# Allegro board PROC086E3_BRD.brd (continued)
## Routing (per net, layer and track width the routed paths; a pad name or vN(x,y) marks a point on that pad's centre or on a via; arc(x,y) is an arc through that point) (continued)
LI_VIN_DATA2: length 23.7
  TOP w0.178: v1(60.07,185.11) 60.07,184.77 59.89,184.59 59.28,184.59 58.92,184.23 58.92,181.87 59.26,181.53 60.45,181.53 60.6,181.38 60.6,181.16 60.45,181 59.26,181 59.11,180.84 59.11,180.62 59.26,180.47 60.45,180.47 60.6,180.31 60.6,180.09 60.45,179.93 59.26,179.93 59.11,179.78 59.11,178.93 58.93,178.75 53.98,178.75 53.74,178.52 U6.44
  BOTTOM w0.178: J6.24 v1(60.07,185.11)
LI_VIN_DATA3: length 23.9
  TOP w0.178: v1(60.57,178.57) 60.36,178.37 54.32,178.37 54.14,178.19 U6.43
  BOTTOM w0.178: v1(60.57,178.57) 60.57,177.57 59.74,176.74 56.79,176.74 56.62,176.92 56.62,177.17 56.79,177.35 59.59,177.35 59.92,177.68 59.92,178.8 60.57,179.45 J6.23
LI_VIN_DATA4: length 23.6
  TOP w0.178: U6.41 54.94,177.74 55.14,177.94 60.89,177.94 61.07,178.11 61.07,181.91 60.91,182.07 59.72,182.07 59.56,182.23 59.56,182.45 59.72,182.6 60.91,182.6 61.07,182.76 61.07,182.98 60.91,183.14 59.72,183.14 59.56,183.29 59.56,183.51 59.72,183.67 60.91,183.67 61.07,183.83 v1(61.07,185.11)
  BOTTOM w0.178: J6.22 v1(61.07,185.11)
LI_VIN_DATA5: length 23.9
  TOP w0.178: U6.40 55.34,177.35 55.52,177.53 61.34,177.53 61.57,177.76 61.57,179.05 v1(61.57,179.05)
  BOTTOM w0.178: J6.21 61.57,180.12 62.33,179.36 63.47,179.36 63.63,179.2 63.63,178.98 63.47,178.82 62.33,178.82 62.18,178.67 62.18,178.45 62.33,178.29 63.47,178.29 63.63,178.13 63.63,177.91 63.47,177.76 62.33,177.76 62.18,177.6 62.18,176.79 62,176.61 61.75,176.61 61.57,176.79 v1(61.57,179.05)
LI_VIN_DATA6: length 23.6
  TOP w0.178: U6.38 56.14,174.92 55.99,175.08 55.88,175.08 55.72,175.24 55.72,175.46 55.88,175.61 55.99,175.61 56.14,175.77 56.14,175.99 55.99,176.15 55.88,176.15 55.72,176.3 55.72,176.52 55.88,176.68 55.99,176.68 56.14,176.84 56.14,176.94 56.32,177.12 61.82,177.12 62.07,177.37 62.07,179.55 61.91,179.7 61.68,179.7 61.52,179.86 61.52,180.08 61.68,180.24 61.91,180.24 62.07,180.39 62.07,180.62 61.91,180.77 61.68,180.77 61.52,180.93 61.52,181.15 61.68,181.3 61.91,181.3 62.07,181.46 62.07,181.68 61.91,181.84 61.73,181.84 61.57,181.99 61.57,186.13 61.75,186.3 v1(62.07,186.3)
  BOTTOM w0.178: J6.20 v1(62.07,186.3)
LI_VIN_DATA7: length 23.7
  TOP w0.178: U6.37 56.54,176.56 56.72,176.74 61.9,176.74 62.03,176.61 62.03,174.51 62.16,174.38 62.41,174.38 62.57,174.54 62.57,181.79 62.04,182.31 62.04,183.62 62.26,183.83 62.51,183.83 62.68,183.65 62.68,182.7 v1(62.57,182.58)
  BOTTOM w0.178: J6.19 v1(62.57,182.58)
LI_VIN_DATA8: length 23.9
  TOP w0.178: U7.47 63.85,174.93 63.69,175.08 63.11,175.08 62.95,175.24 62.95,175.46 63.11,175.62 63.69,175.62 63.85,175.77 63.85,175.99 63.69,176.15 63.11,176.15 62.95,176.31 62.95,176.53 63.11,176.68 63.69,176.68 63.85,176.84 63.85,177.06 63.69,177.22 63.11,177.22 62.95,177.37 62.95,177.59 63.11,177.75 63.69,177.75 63.85,177.91 63.85,178.22 63.07,179 63.07,184.96 62.91,185.12 62.11,185.12 61.95,185.28 61.95,185.5 62.11,185.65 62.91,185.65 63.07,185.81 v1(63.07,186.3)
  BOTTOM w0.178: v1(63.07,186.3) 63.2,186.43 63.2,187.1 63.02,187.28 62.76,187.28 62.59,187.1 62.59,185.71 63.07,185.23 J6.18
LI_VIN_DATA9: length 23.5
  TOP w0.178: U7.46 64.25,174.9 v1(64.44,175.09)
  L03_SIG1 w0.107: v1(64.57,179.79) 64.44,179.66 64.44,179.37 64.35,179.28 63.16,179.28 63.07,179.18 63.07,179.05 63.16,178.96 64.35,178.96 64.44,178.86 64.44,178.73 64.35,178.64 63.16,178.64 63.07,178.54 63.07,178.41 63.16,178.32 64.35,178.32 64.44,178.22 64.44,178.09 64.35,178 63.16,178 63.07,177.9 63.07,177.77 63.16,177.68 64.35,177.68 64.44,177.58 64.44,177.45 64.35,177.36 63.16,177.36 63.07,177.26 63.07,177.13 63.16,177.04 64.35,177.04 64.44,176.94 64.44,176.81 64.35,176.72 63.16,176.72 63.07,176.62 63.07,176.49 63.16,176.4 64.35,176.4 64.44,176.3 64.44,176.17 64.35,176.08 63.16,176.08 63.07,175.98 63.07,175.85 63.16,175.76 64.35,175.76 64.44,175.66 v1(64.44,175.09)
  BOTTOM w0.178: J6.17 63.57,179.97 63.75,179.79 v1(64.57,179.79)
LI_VIN_DATA10: length 23.8
  TOP w0.178: v1(64.07,186.3) 63.5,185.74 63.5,185.41 63.66,185.25 65.2,185.25 65.35,185.09 65.35,184.87 65.2,184.72 63.66,184.72 63.5,184.56 63.5,184.34 63.66,184.18 65.2,184.18 65.35,184.03 65.35,183.81 65.2,183.65 63.66,183.65 63.5,183.49 63.5,179.13 63.79,178.84 64.63,178.84 65.05,178.42 65.05,176.82 64.89,176.66 64.55,176.66 64.39,176.51 64.39,176.29 64.55,176.13 64.89,176.13 65.05,175.97 U7.44
  BOTTOM w0.178: J6.16 v1(64.07,186.3)
LI_VIN_DATA11: length 23.8
  TOP w0.178: v1(65.66,175.14) 65.45,174.93 U7.43
  L03_SIG1 w0.107: v1(64.57,182.58) 64.57,180.78 65.66,179.69 65.66,179.29 65.75,179.19 66.99,179.19 67.08,179.1 67.08,178.97 66.99,178.87 65.75,178.87 65.66,178.78 65.66,178.65 65.75,178.55 66.99,178.55 67.08,178.46 67.08,178.33 66.99,178.23 65.75,178.23 65.66,178.14 65.66,178.01 65.75,177.91 66.99,177.91 67.08,177.82 67.08,177.69 66.99,177.59 65.75,177.59 65.66,177.5 65.66,177.37 65.75,177.27 66.99,177.27 67.08,177.18 67.08,177.05 66.99,176.95 65.75,176.95 65.66,176.86 65.66,176.73 65.75,176.63 66.99,176.63 67.08,176.54 67.08,176.41 66.99,176.31 65.75,176.31 65.66,176.22 v1(65.66,175.14)
  BOTTOM w0.178: J6.15 v1(64.57,182.58)
LI_VIN_DATA12: length 23.9
  TOP w0.178: U7.41 66.25,175.63 v1(66.37,175.75)
  L03_SIG1 w0.107: v1(65.07,186.3) 65.07,180.91 65.23,180.75 65.45,180.75 65.54,180.85 65.54,181.73 65.64,181.82 65.77,181.82 65.86,181.73 65.86,180.85 65.96,180.75 66.09,180.75 66.18,180.85 66.18,181.73 66.28,181.82 66.41,181.82 66.5,181.73 66.5,180.85 66.6,180.75 66.73,180.75 66.82,180.85 66.82,181.73 66.92,181.82 67.05,181.82 67.14,181.73 67.14,180.85 67.24,180.75 67.43,180.75 67.54,180.65 67.54,176.08 67.21,175.75 v1(66.37,175.75)
  BOTTOM w0.178: J6.14 v1(65.07,186.3)
LI_VIN_DATA13: length 23.9
  TOP w0.178: U7.40 66.65,174.91 v1(66.88,175.14)
  L03_SIG1 w0.107: v1(65.57,182.58) 67.77,182.58 68,182.35 68,181.02 68.09,180.93 68.59,180.93 68.68,180.84 68.68,180.7 68.59,180.61 68.09,180.61 68,180.52 68,180.38 68.09,180.29 68.59,180.29 68.68,180.2 68.68,180.06 68.59,179.97 68.09,179.97 68,179.88 68,179.74 68.09,179.65 68.59,179.65 68.68,179.56 68.68,179.42 68.59,179.33 68.09,179.33 68,179.24 68,179.1 68.09,179.01 68.59,179.01 68.68,178.92 68.68,178.78 68.59,178.69 68.09,178.69 68,178.6 68,178.46 68.09,178.37 68.59,178.37 68.68,178.28 68.68,178.14 68.59,178.05 68.09,178.05 68,177.96 68,177.82 68.09,177.73 68.59,177.73 68.68,177.64 68.68,177.5 68.59,177.41 68.09,177.41 68,177.32 68,177.18 68.09,177.09 68.59,177.09 68.68,177 68.68,176.86 68.59,176.77 68.09,176.77 68,176.68 68,176.54 68.09,176.45 68.59,176.45 68.68,176.36 68.68,176.22 68.59,176.13 68.09,176.13 68,176.04 68,175.9 68.09,175.81 68.59,175.81 68.68,175.72 68.68,175.58 68.59,175.49 68.09,175.49 67.74,175.14 v1(66.88,175.14)
  BOTTOM w0.178: J6.13 v1(65.57,182.58)
LI_VIN_HD: length 26
  TOP w0.178: v1(66.07,186.29) 66.07,181.85 65.79,181.57 64.27,181.57 64.09,181.39 64.09,180.93 64.27,180.75 65.5,180.75 65.68,180.58 65.68,179.47 65.9,179.26 67.27,179.26 67.45,179.08 67.45,178.16 67.29,178 65.76,178 65.61,177.85 65.61,177.63 65.76,177.47 67.29,177.47 67.45,177.31 67.45,177.09 67.29,176.94 65.76,176.94 65.61,176.78 65.61,176.56 65.76,176.4 67.29,176.4 67.45,176.25 U7.38
  BOTTOM w0.178: J6.12 v1(66.07,186.29)
LI_VIN_PCLK: length 22.2
  TOP w0.178: U5.4 48.92,174.81 49.38,175.27 v1(49.56,175.27)
  BOTTOM w0.178: R324.1 TP26.1 66.04,176.94 64.82,175.73 50.01,175.73 v1(49.56,175.27)
LI_VIN_VD: length 23.8
  TOP w0.178: U7.37 67.85,179.95 68.2,180.3 68.2,180.81 68.04,180.97 67.21,180.97 67.06,181.12 67.06,181.34 67.21,181.5 68.04,181.5 68.2,181.66 68.2,181.88 68.04,182.03 67.21,182.03 67.06,182.19 67.06,182.41 67.21,182.57 68.04,182.57 68.2,182.72 68.2,183.04 67.94,183.29 66.98,183.29 66.73,183.04 v1(66.73,179.79)
  BOTTOM w0.178: J6.11 66.57,180.47 65.41,179.31 65.41,178.62 TP24.1 66.55,178.47 66.73,178.65 v1(66.73,179.79)
LINA_L_A: length 2.8
  BOTTOM w0.381: U51.1 16.13,78.1 16,78.23 C331.2 16,79.86 R447.1
LINA_L_B: length 6.4
  BOTTOM w0.381: R448.1 18.03,78.7 C331.1 16.92,78.23 16.78,78.1 U51.2 16.78,76.09 16.24,75.55 R449.2
LINA_L_C: length 8.1
  BOTTOM w0.381: R445.1 20.82,73.3 21.04,73.07 21.04,71.74 20.42,71.12 R441.1 17.71,71.12 C327.1 17.57,71.76 17.43,71.9 U51.6
LINA_L_D: length 2.8
  BOTTOM w0.381: U51.7 16.78,71.88 16.65,71.75 C327.2 16.65,70.04 R442.1
LINA_R_A: length 2.8
  BOTTOM w0.381: R212.1 27.91,76.34 C135.2 27.87,75.77 28.01,75.63 U26.1
LINA_R_B: length 6.4
  BOTTOM w0.381: R211.1 30.03,76.42 28.92,76.42 C135.1 28.79,75.76 28.66,75.63 U26.2 28.66,74.74 28.66,73.63 28.18,73.15 R210.2
LINA_R_C: length 7.3
  BOTTOM w0.381: U26.6 29.31,69.51 29.44,69.38 C142.1 29.59,68.72 R222.1 31.31,68.72 32.11,69.52 32.11,70.75 31.67,71.18 R217.1
LINA_R_D: length 2.8
  BOTTOM w0.381: R221.1 28.52,67.64 C142.2 28.52,69.34 28.66,69.47 U26.7
LINB_L_A: length 2.9
  TOP w0.381: R455.1 18.39,78.91 C337.2 18.18,78.17 18.08,78.08 U52.1
LINB_L_B: length 4
  TOP w0.381: U52.2 17.43,78.03 17.26,78.2 C337.1 17.26,79.87 R456.1 R457.2
LINB_L_C: length 8.2
  TOP w0.381: R450.1 16.71,70.03 C333.1 16.71,71.78 16.78,71.85 U52.6 16.78,73.93 17.32,74.46 R452.1
LINB_L_D: length 2.9
  TOP w0.381: U52.7 17.43,71.92 17.63,71.72 C333.2 17.85,71.05 R451.1
LINB_R_A: length 2.9
  TOP w0.381: U24.1 29.96,75.62 30.05,75.71 C123.2 30.27,76.51 R202.1
LINB_R_B: length 4
  TOP w0.381: R200.2 R201.1 29.13,77.47 C123.1 29.13,75.81 29.31,75.64 U24.2
LINB_R_C: length 8.4
  TOP w0.381: R205.1 29.19,72.06 28.66,71.53 U24.6 28.66,69.47 28.58,69.4 C129.1 28.58,67.63 R209.1
LINB_R_D: length 2.9
  TOP w0.381: R207.1 30.54,68.87 C129.2 29.5,69.32 29.31,69.52 U24.7
MCASP0_ACLKX: length 31.6
  TOP w0.178: J1.57 83.5,108.51 82.67,109.33 v1(81.97,109.33)
  L03_SIG1 w0.107: v1(81.97,109.33) 80.31,109.33 73.41,102.42 73.41,99.53 v1(66.67,92.8)
  BOTTOM w0.178: U21.2 64.91,94.84 65.91,93.84 U21.5 v1(66.67,92.8)
MCASP0_AFSX: length 193.8
  TOP w0.178: J1.59 85.09,109.05 v1(85.09,109.63) ; U19.6 59.5,105.89 60,106.39 v1(60.44,106.39) ; v1(66.32,41.99) 66.32,41.97 65.46,41.11 62.03,41.11 61.2,41.93 U32.35 ; U19.35 43.41,109.89 v1(43.41,109.89) ; U32.6 v1(45.44,45.93)
  L03_SIG1 w0.107: v1(66.32,41.99) 68.55,41.99 73.89,47.33 73.89,58.5 73.78,58.61 73.14,58.61 73.04,58.72 73.04,64.62 73.14,64.73 73.36,64.73 73.46,64.62 73.46,59.14 73.57,59.04 73.78,59.04 73.89,59.14 73.89,73.64 81.61,81.36 81.61,103.57 85.09,107.05 v1(85.09,109.63)
  L08_SIG2 w0.107: v1(60.44,106.39) 60.65,106.18 62.53,106.18 63.14,106.79 63.14,109.28 61.49,110.93 49.36,110.93 49.26,111.04 49.26,111.25 49.36,111.36 52.78,111.36 52.88,111.46 52.88,111.68 52.78,111.78 48.94,111.78 48.83,111.68 48.83,111.04 48.72,110.93 47.88,110.93 46.84,109.89 v1(43.41,109.89)
  BOTTOM w0.178: v1(66.32,41.99) 66.32,41.97 65.89,41.54 62.15,41.54 61.61,42.08 55.97,42.08 55.46,41.58 45.21,41.58 44.63,42.16 44.63,45.12 v1(45.44,45.93) ; v1(85.09,109.63) 84.25,108.8 62.85,108.8 v1(60.44,106.39)
MCASP0_AXR0: length 117.1
  TOP w0.178: J1.69 84.04,116.51 v1(84.02,116.49) ; v1(60.78,43.43) 60.28,42.93 U32.37
  L03_SIG1 w0.107: v1(84.02,116.49) 84.58,115.93 84.58,107.07 81.28,103.77 81.28,85.15 74.2,78.07 74.2,77.92 74.35,77.77 74.51,77.77 77.88,81.14 78.03,81.14 78.17,81 78.17,80.84 74.81,77.47 74.81,77.32 74.96,77.17 75.11,77.17 78.6,80.66 78.76,80.66 78.91,80.51 78.91,80.36 75.11,76.56 74.96,76.56 73.9,77.62 73.75,77.62 71.98,75.85 71.98,57.87 73.56,56.29 73.56,47.57 68.9,42.91 61.31,42.91 v1(60.78,43.43)
MCASP0_AXR1: length 118.4
  TOP w0.178: U32.38 v1(59.51,43.43) ; J1.77 83.83,118.51 v1(82.96,117.64)
  L03_SIG1 w0.107: v1(59.51,43.43) 60.37,42.58 64.59,42.58 65.71,41.46 68.53,41.46 74.22,47.15 74.22,73.44 81.97,81.19 81.97,86.55 82.07,86.65 83.69,86.65 83.79,86.76 83.79,86.99 83.68,87.1 82.07,87.1 81.97,87.21 81.97,87.44 82.07,87.55 83.34,87.55 83.44,87.66 83.44,87.89 83.34,88 82.07,88 81.97,88.11 81.97,88.34 82.07,88.45 83.34,88.45 83.44,88.56 83.44,88.79 83.34,88.9 82.07,88.9 81.97,89.01 81.97,89.24 82.07,89.35 83.34,89.35 83.44,89.46 83.44,89.69 83.34,89.8 82.07,89.8 81.97,89.91 81.97,90.14 82.07,90.25 83.34,90.25 83.44,90.36 83.44,90.59 83.34,90.7 82.07,90.7 81.97,90.81 81.97,91.04 82.07,91.15 83.34,91.15 83.44,91.25 83.44,91.49 83.34,91.6 82.07,91.6 81.97,91.7 81.97,91.94 82.07,92.05 83.34,92.05 83.44,92.15 83.44,92.39 83.34,92.5 82.07,92.5 81.97,92.6 81.97,103.29 85.57,106.89 85.57,115.96 84.44,117.09 83.5,117.09 v1(82.96,117.64)
MCASP0_AXR2: length 118.2
  TOP w0.178: v1(60.78,44.43) 60.28,43.93 U32.39 ; J1.71 83.5,117.01 82.99,116.51 v1(82.99,116.49)
  L03_SIG1 w0.107: v1(82.99,116.49) 82.99,116.13 83.48,115.64 83.48,114.31 83.92,113.87 83.92,107.46 80.62,104.16 80.62,94.97 73.09,87.44 73.09,87.29 73.24,87.14 73.39,87.14 77.86,91.61 78.02,91.61 78.17,91.46 78.17,91.31 74.7,87.85 74.7,87.69 74.85,87.54 75,87.54 78.47,91.01 78.62,91.01 78.77,90.86 78.77,90.71 71.85,83.79 71.85,76.94 71.02,76.11 71.02,57.87 72.9,55.99 72.9,48.67 70.36,46.13 70.36,45.33 68.95,43.92 62.18,43.92 61.67,44.43 v1(60.78,44.43)
MCASP0_AXR3: length 117.1
  TOP w0.178: v1(84.04,114.45) 84.1,114.51 J1.61 ; U32.40 v1(59.51,44.43)
  L03_SIG1 w0.107: v1(84.04,114.45) 84.09,114.45 84.25,114.29 84.25,107.2 80.95,103.9 80.95,85.48 78.01,82.54 77.86,82.54 77.71,82.7 77.71,82.85 80.19,85.32 80.19,85.48 80.04,85.63 79.89,85.63 77.41,83.15 77.26,83.15 77.11,83.3 77.11,83.45 79.59,85.93 79.59,86.08 79.44,86.23 79.29,86.23 76.81,83.75 76.66,83.75 76.51,83.9 76.51,84.05 78.64,86.19 78.64,86.36 78.5,86.5 78.35,86.5 75.9,84.05 75.9,83.9 77.56,82.24 77.56,82.09 71.37,75.9 71.37,57.97 73.23,56.12 73.23,47.75 68.91,43.43 61.99,43.43 61.5,43.92 60.02,43.92 v1(59.51,44.43)
MCASP0_AXR4: length 114.1
  TOP w0.178: R270.2 v1(42.37,45.55) ; v1(83.82,117.64) 83.85,117.64 83.97,117.51 J1.73
  L03_SIG1 w0.107: v1(42.37,45.55) 42.4,45.55 42.79,45.15 47.42,45.15 48.9,46.63 56.53,46.63 56.85,46.95 61.03,46.95 62.63,45.35 67.94,45.35 71.68,49.09 71.68,55.32 68.73,58.28 68.73,87.84 75.37,94.48 75.37,103.42 80.8,108.84 83.33,108.84 83.59,109.1 83.59,113.71 82.47,114.82 82.47,117.87 82.72,118.11 83.34,118.11 v1(83.82,117.64)
MCASP0_AXR4_R: length 3.1
  TOP w0.178: U32.8 44.89,44.93 44.27,45.55 R270.1
MCASP0_AXR5: length 115.5
  TOP w0.178: v1(81.98,108.01) 82.48,107.51 J1.53 ; R274.2 v1(42.21,44.43)
  L03_SIG1 w0.107: v1(81.98,108.01) 80.67,108.01 75.95,103.29 75.95,102.46 76.06,102.36 77.11,102.36 77.22,102.25 77.22,102.01 77.11,101.91 76.06,101.91 75.95,101.8 75.95,101.57 76.06,101.46 77.11,101.46 77.22,101.35 77.22,101.12 77.11,101.01 76.06,101.01 75.95,100.9 75.95,100.67 76.06,100.56 77.11,100.56 77.22,100.45 77.22,100.22 77.11,100.11 76.06,100.11 75.95,100 75.95,99.77 76.06,99.66 77.11,99.66 77.22,99.55 77.22,99.32 77.11,99.21 76.06,99.21 75.95,99.1 75.95,98.87 76.06,98.76 77.11,98.76 77.23,98.64 77.23,98.43 77.11,98.31 76.06,98.31 75.95,98.2 75.95,93.79 70.41,88.25 70.41,82.51 69.06,81.16 69.06,58.45 72.04,55.48 72.04,48.93 69.65,46.54 69.65,45.73 68.86,44.94 62.39,44.94 60.8,46.53 57.9,46.53 56.84,45.47 48.77,45.47 47.74,44.43 42.21,44.43 v1(42.21,44.43)
MCASP0_AXR5_R: length 2.9
  TOP w0.178: U32.9 R274.1
MCASP0_AXR6: length 114.9
  TOP w0.178: J1.55 v1(83.02,108.01) ; R276.2 v1(42.22,43.31)
  L03_SIG1 w0.107: v1(42.22,43.31) 42.22,43.32 42.87,43.97 56.66,43.97 57.63,44.94 61.7,44.94 62.21,44.43 68.9,44.43 70,45.54 70,46.39 72.4,48.78 72.4,55.63 69.85,58.17 69.85,58.67 69.96,58.78 70.6,58.78 70.7,58.89 70.7,64.43 70.6,64.54 70.38,64.54 70.28,64.43 70.28,59.31 70.17,59.21 69.96,59.21 69.85,59.31 69.85,76.2 70.76,77.11 70.76,85.56 79.93,94.72 79.93,106.5 80.68,107.25 82.26,107.25 v1(83.02,108.01)
MCASP0_AXR6_R: length 3.1
  TOP w0.178: U32.10 44.89,43.93 44.27,43.31 R276.1
MCASP0_AXR7: length 62.7
  TOP w0.178: J1.72 v1(92.41,117.01) ; U19.37 44.74,108.89 v1(44.24,109.39)
  L03_SIG1 w0.107: v1(44.24,109.39) 44.82,108.8 44.82,108.35 45.27,107.91 45.88,107.91 46.14,107.65 46.47,107.65 46.58,107.75 46.58,108.28 46.68,108.39 46.92,108.39 47.02,108.28 47.02,107.75 47.13,107.65 47.37,107.65 47.47,107.75 47.47,108.28 47.58,108.39 47.82,108.39 47.92,108.28 47.92,107.75 48.03,107.65 57.94,107.65 58.32,107.26 61.5,107.26 65.27,103.5 73.77,103.5 80.37,110.09 v1(81.97,110.09)
  L08_SIG2 w0.107: v1(92.41,117.01) 90.2,117.01 83.82,110.63 82.5,110.63 v1(81.97,110.09)
MCASP0_AXR8: length 63.9
  TOP w0.178: U19.38 v1(45.51,108.39) ; J1.70 92.94,116.51 v1(93.44,116.01)
  L03_SIG1 w0.107: v1(82.98,110.09) 82.98,110.4 82.76,110.63 80.29,110.63 73.49,103.83 65.57,103.83 61.65,107.75 58.5,107.75 57.25,109 48.81,109 48.7,109.11 48.7,109.73 48.59,109.84 48.36,109.84 48.25,109.73 48.25,109.11 48.14,109 47.91,109 47.8,109.11 47.8,109.73 47.69,109.84 47.46,109.84 47.35,109.73 47.35,109.11 47.24,109 47.01,109 46.9,109.11 46.9,109.73 46.79,109.84 46.56,109.84 46.45,109.73 46.45,109.11 46.34,109 45.82,109 45.51,108.69 v1(45.51,108.39)
  L08_SIG2 w0.107: v1(82.98,110.09) 83.97,110.09 89.89,116.01 v1(93.44,116.01)
MCASP0_AXR9: length 62.7
  TOP w0.178: v1(44.24,108.39) 44.74,107.89 U19.39 ; J1.78 v1(92.41,118.51)
  L03_SIG1 w0.107: v1(82.97,112.56) 82.97,111.94 82.12,111.08 80.09,111.08 73.33,104.33 65.8,104.33 61.82,108.31 58.67,108.31 56.84,110.15 44.33,110.15 43.72,109.54 43.72,108.91 v1(44.24,108.39)
  L08_SIG2 w0.107: v1(82.97,112.56) 84.63,112.56 90.59,118.51 v1(92.41,118.51)
MCASP0_AXR10: length 64
  TOP w0.178: U19.40 v1(45.51,107.39) ; J1.76 92.94,118.01 v1(93.44,118.51)
  L03_SIG1 w0.107: v1(81.96,113.6) 75.99,113.6 72.61,110.22 68.66,110.22 67.89,109.46 59.73,109.46 58.47,110.71 43.25,110.71 42.79,110.25 42.79,109.13 44.02,107.9 44.41,107.9 44.92,107.39 v1(45.51,107.39)
  L08_SIG2 w0.107: v1(81.96,113.6) 82.47,113.09 84.56,113.09 90.55,119.08 92.87,119.08 v1(93.44,118.51)
MCASP0_AXR11: length 58.5
  TOP w0.178: R161.2 64.56,105.76 v1(64.83,106.03) ; v1(93.44,117.01) 92.94,117.51 J1.74
  L03_SIG1 w0.107: v1(64.83,106.03) 65.1,106.29 65.1,107.03 64.68,107.45 64.31,107.45 64.02,107.73 64.02,108.4 64.42,108.8 65.93,108.8 66.03,108.69 66.03,107 66.14,106.89 66.35,106.89 66.48,107.02 66.48,108.69 66.59,108.8 66.93,108.8 67.41,108.32 67.41,107.51 67.52,107.41 67.75,107.41 67.86,107.51 67.86,108.26 67.97,108.37 68.2,108.37 68.31,108.26 68.31,107.51 68.42,107.41 68.65,107.41 68.76,107.51 68.76,108.26 68.87,108.37 69.1,108.37 69.21,108.26 69.21,107.51 69.32,107.41 69.55,107.41 69.66,107.51 69.66,108.26 69.77,108.37 71.32,108.37 71.43,108.26 71.43,107.45 71.53,107.34 71.77,107.34 71.88,107.45 71.88,108.26 71.98,108.37 72.22,108.37 72.33,108.26 72.33,107.45 72.43,107.34 72.67,107.34 72.78,107.45 72.78,108.26 72.88,108.37 73.12,108.37 73.23,108.26 73.23,107.45 73.33,107.34 73.57,107.34 73.68,107.45 73.68,108.26 73.78,108.37 74,108.37 74.11,108.26 74.11,107.42 74.22,107.31 74.45,107.31 74.56,107.42 74.56,108.26 74.67,108.37 74.89,108.37 74.99,108.26 74.99,107.57 75.11,107.45 75.34,107.45 75.44,107.56 75.44,108.26 75.55,108.37 76.16,108.37 80.35,112.56 v1(81.96,112.56)
  L08_SIG2 w0.107: v1(81.96,112.56) 82.72,111.79 84.51,111.79 90.27,117.56 92.89,117.56 v1(93.44,117.01)
MCASP0_AXR11_R: length 5.4
  TOP w0.178: U19.8 61.12,106.89 62.24,105.76 R161.1
MCASP0_AXR12: length 58.8
  TOP w0.178: R157.2 v1(64.52,106.88) ; J1.80 92.94,119.01 v1(93.44,119.51)
  L03_SIG1 w0.107: v1(64.52,106.88) 64.25,106.88 63.59,107.54 63.59,108.47 64.25,109.13 67.06,109.13 67.46,108.72 71.66,108.72 71.76,108.83 71.76,109.77 71.87,109.88 72.1,109.88 72.21,109.77 72.21,108.83 72.32,108.72 72.55,108.72 72.66,108.83 72.66,109.77 72.77,109.88 73,109.88 73.11,109.77 73.11,108.83 73.22,108.72 73.45,108.72 73.56,108.83 73.56,109.77 73.67,109.88 73.9,109.88 74.01,109.77 74.01,108.83 74.12,108.72 74.35,108.72 74.46,108.83 74.46,109.77 74.57,109.88 74.8,109.88 74.91,109.77 74.91,108.83 75.02,108.72 75.78,108.72 76.16,109.1 76.16,109.72 76.27,109.83 77.18,109.83 77.3,109.95 77.3,110.17 77.19,110.28 76.27,110.28 76.16,110.38 76.16,110.72 76.27,110.83 77.78,110.83 77.88,110.94 77.88,111.17 77.78,111.28 76.27,111.28 76.16,111.39 76.16,111.62 76.27,111.73 77.78,111.73 77.88,111.84 77.88,112.07 77.78,112.18 76.27,112.18 76.16,112.29 76.16,112.72 76.54,113.09 82.47,113.09 v1(82.97,113.6)
  L08_SIG2 w0.107: v1(82.97,113.6) 84.48,113.6 90.39,119.51 v1(93.44,119.51)
MCASP0_AXR12_R: length 5.1
  TOP w0.178: U19.9 61.25,107.39 61.76,106.88 R157.1
MCASP0_AXR13: length 57.8
  TOP w0.178: J1.102 92.45,124.51 v1(92.48,124.54) ; R154.2 v1(64.52,108)
  L03_SIG1 w0.107: v1(64.52,108) 65.32,108 65.62,107.7 65.62,105.85 65.82,105.64 66.95,105.64 67.08,105.78 67.08,106.72 67.24,106.88 67.59,106.88 67.7,106.77 67.7,106.2 67.81,106.09 68.03,106.09 68.15,106.22 68.15,106.77 68.26,106.88 68.79,106.88 68.9,106.77 68.9,105.64 69.02,105.53 69.23,105.53 69.35,105.65 69.35,106.77 69.46,106.88 70.7,106.88 70.81,106.77 70.81,105.61 70.92,105.5 71.15,105.5 71.26,105.61 71.26,106.77 71.37,106.88 71.6,106.88 71.71,106.77 71.71,105.61 71.82,105.5 72.05,105.5 72.16,105.61 72.16,106.77 72.27,106.88 72.5,106.88 72.61,106.77 72.61,105.61 72.72,105.5 72.95,105.5 73.06,105.61 73.06,106.77 73.17,106.88 73.4,106.88 73.51,106.77 73.51,105.61 73.62,105.5 73.85,105.5 73.96,105.61 73.96,106.77 74.07,106.88 75.22,106.88 79.93,111.59 v1(81.97,111.59)
  L08_SIG2 w0.107: v1(92.48,124.54) 91.64,123.71 91.64,121.27 84.32,113.94 83.52,113.94 83.38,114.08 81.74,114.08 81.33,113.67 81.33,112.23 v1(81.97,111.59)
MCASP0_AXR13_R: length 4.9
  TOP w0.178: U19.10 62.31,107.89 62.42,108 R154.1
MCASP1_ACLKX: length 183.1
  TOP w0.178: v1(25.63,173.82) 25.08,173.82 R19.1 ; J1.110 v1(92.41,126.51)
  L08_SIG2 w0.107: v1(81.99,130.79) 76.12,130.79 72.54,134.37 72.54,138.64 71.66,139.52 60.74,139.52 58.87,141.39 52.91,141.39 52.81,141.48 52.81,141.62 52.91,141.71 58.78,141.71 58.87,141.8 58.87,141.94 58.78,142.03 52.91,142.03 52.81,142.12 52.81,142.26 52.91,142.35 58.78,142.35 58.87,142.44 58.87,142.58 58.78,142.67 52.59,142.67 52.49,142.58 52.49,141.48 52.4,141.39 50.93,141.39 49.33,142.99 49.33,148.78 49.23,148.87 49.1,148.87 49.01,148.78 49.01,145.71 48.91,145.62 48.78,145.62 48.69,145.71 48.69,148.78 48.59,148.87 48.46,148.87 48.37,148.78 48.37,145.71 48.27,145.62 48.14,145.62 48.05,145.71 48.05,148.78 47.95,148.87 47.82,148.87 47.73,148.78 47.73,145.71 47.63,145.62 47.5,145.62 47.41,145.71 47.41,148.78 47.31,148.87 47.18,148.87 47.09,148.78 47.09,145.71 46.99,145.62 46.86,145.62 46.77,145.71 46.77,149.1 46.86,149.19 49.23,149.19 49.33,149.29 49.33,149.67 45.72,153.27 44.94,153.27 43.21,155 38.48,155 38.38,155.1 38.38,155.23 38.48,155.33 39.79,155.33 39.88,155.42 39.88,155.55 39.79,155.65 38.48,155.65 38.38,155.74 38.38,155.87 38.48,155.97 39.79,155.97 39.88,156.06 39.88,156.19 39.79,156.29 38.48,156.29 38.38,156.38 38.38,156.51 38.48,156.61 39.79,156.61 39.88,156.7 39.88,156.83 39.79,156.93 38.16,156.93 38.06,156.83 38.06,155.05 37.96,154.95 36.63,154.95 35.18,156.4 35.18,158.14 35.09,158.24 34.95,158.24 34.86,158.14 34.86,156.71 34.77,156.62 34.63,156.62 34.54,156.71 34.54,158.46 34.63,158.56 35.09,158.56 35.18,158.65 35.18,166.99 34.21,167.95 33.72,167.95 33.63,168.05 33.63,169.83 33.32,170.14 32.99,170.14 32.69,169.84 32.69,168.05 32.6,167.95 31.83,167.95 31.73,168.05 31.73,169.47 31.42,169.78 31.15,169.78 30.84,169.47 30.84,168.06 30.73,167.95 30.23,167.95 29.72,168.46 29.72,171.07 29.1,171.69 26.04,171.69 25.63,172.09 v1(25.63,173.82)
  BOTTOM w0.178: v1(81.99,130.79) 83.19,130.79 87.47,126.51 v1(92.41,126.51)
MCASP1_AFSX: length 186.6
  TOP w0.178: U2.39 24.08,186.24 25.3,187.46 v1(25.3,188.97) ; J1.60 v1(92.41,109.01)
  L08_SIG2 w0.107: v1(25.3,188.97) 26.05,188.22 28.96,188.22 30.07,189.34 43.03,189.34 44.2,188.17 44.2,184.01 45.11,183.09 45.11,177.2 44.25,176.34 44.25,172.42 45.47,171.2 45.47,166.2 43.89,164.63 43.89,162.52 44.6,161.81 48.34,161.81 65.74,144.41 83.95,144.41 85.75,142.6 85.75,138.34 91.16,132.92 91.16,132.79 91.07,132.7 90.94,132.7 87.13,136.51 87,136.51 86.9,136.41 86.9,136.28 90.71,132.47 90.71,132.34 90.62,132.25 90.48,132.25 86.68,136.05 86.54,136.05 86.45,135.96 86.45,135.83 90.26,132.02 90.26,131.89 90.16,131.79 90.03,131.79 86.22,135.6 86.09,135.6 86,135.51 86,135.37 90.03,131.34 90.16,131.34 90.54,131.72 91.1,131.72 91.21,131.61 91.21,127.39 91.3,127.29 91.43,127.29 91.53,127.39 91.53,131.19 91.62,131.28 91.75,131.28 91.85,131.19 91.85,126.35 93.45,124.75 93.45,123.91 94.67,122.69 94.67,113.44 93.95,112.73 93.95,108.82 93.64,108.51 92.91,108.51 v1(92.41,109.01)
MCASP1_AXR0: length 187.1
  TOP w0.178: J1.13 83.5,97.51 v1(83,97.01) ; U2.37 25.08,185.92 v1(25.58,186.42)
  L08_SIG2 w0.107: v1(83,97.01) 83.55,97.56 83.55,99.49 74.98,108.05 74.98,113.09 74.07,114 74.07,118.47 75.39,119.79 76.71,119.79 77.06,120.15 77.06,121.83 73.71,125.18 73.71,127.31 71.27,129.75 69.39,129.75 67.97,131.17 67.97,132.95 65.89,135.03 65.89,138.39 65.68,138.59 56.35,138.59 56.26,138.5 56.26,138.36 56.35,138.27 62.54,138.27 62.64,138.18 62.64,138.04 62.54,137.95 56.03,137.95 55.94,138.04 55.94,138.5 55.84,138.59 52.47,138.59 52.38,138.5 52.38,138.36 52.47,138.27 53.91,138.27 54,138.18 54,138.04 53.91,137.95 52.47,137.95 52.38,137.86 52.38,137.72 52.47,137.63 53.91,137.63 54,137.54 54,137.4 53.91,137.31 52.15,137.31 52.06,137.4 52.06,138.5 51.96,138.59 51.41,138.59 47.17,142.83 47.17,142.96 47.27,143.05 47.4,143.05 49.28,141.17 49.42,141.17 49.51,141.26 49.51,141.4 47.4,143.51 47.27,143.51 46.95,143.19 46.81,143.19 45.77,144.23 45.77,150.23 45.68,150.32 45.54,150.32 45.45,150.23 45.45,149.45 45.36,149.36 45.22,149.36 45.13,149.45 45.13,150.23 45.04,150.32 44.9,150.32 44.81,150.23 44.81,149.45 44.72,149.36 44.58,149.36 44.49,149.45 44.49,150.23 44.4,150.32 44.26,150.32 44.17,150.23 44.17,149.45 44.08,149.36 43.94,149.36 43.85,149.45 43.85,150.23 43.76,150.32 43.62,150.32 43.53,150.23 43.53,149.45 43.44,149.36 43.3,149.36 43.21,149.45 43.21,150.55 43.3,150.64 45.68,150.64 45.77,150.74 45.77,151.09 44.3,152.56 41.54,152.56 41.45,152.47 41.45,152.33 41.54,152.24 43.85,152.24 43.94,152.15 43.94,152.01 43.85,151.92 41.22,151.92 41.13,152.01 41.13,152.47 41.03,152.56 36.07,152.56 34.7,153.93 32.46,153.93 31.44,154.96 31.44,157.73 30.91,158.25 28.6,158.25 24.14,162.71 24.14,164.44 22.91,165.67 22.91,172.88 23.11,173.08 23.11,175.29 23.8,175.98 23.8,184.06 24.89,185.15 24.89,185.73 v1(25.58,186.42)
MCASP1_AXR1: length 187.1
  TOP w0.178: J1.15 v1(84.03,98.01) ; U2.36 v1(25.58,185.48)
  L08_SIG2 w0.107: v1(84.03,98.01) 84.03,99.47 75.29,108.21 75.29,113.22 74.38,114.13 74.38,118.35 75.52,119.48 76.84,119.48 77.37,120.02 77.37,121.96 75.23,124.09 75.23,127.87 74.63,128.48 72.98,128.48 71.4,130.06 69.52,130.06 68.28,131.3 68.28,133.08 66.94,134.42 66.94,137.78 65.81,138.9 51.54,138.9 50.29,140.15 50.29,141.05 47.52,143.82 46.62,143.82 46.08,144.36 46.08,151.22 44.43,152.87 43.48,152.87 42.62,153.73 41.11,153.73 41.02,153.64 41.02,153.5 41.11,153.41 41.56,153.41 41.66,153.32 41.66,153.18 41.56,153.09 40.79,153.09 40.7,153.18 40.7,153.64 40.6,153.73 36.66,153.73 36.56,153.64 36.56,153.5 36.66,153.41 37.6,153.41 37.69,153.32 37.69,153.18 37.6,153.09 36.34,153.09 36.24,153.18 36.24,153.64 36.15,153.73 35.34,153.73 34.82,154.24 33.93,154.24 33.63,154.54 33.63,155.17 33.54,155.26 33.4,155.26 33.31,155.17 33.31,154.64 33.22,154.54 33.08,154.54 32.99,154.64 32.99,155.17 32.9,155.26 32.76,155.26 32.67,155.17 32.67,154.64 32.58,154.54 32.44,154.54 32.35,154.64 32.35,155.49 32.44,155.58 33.54,155.58 33.63,155.67 33.63,156.52 33.02,157.13 33.02,163.64 32.41,164.24 27.94,164.24 27.84,164.34 27.84,164.47 27.94,164.56 32.1,164.56 32.19,164.66 32.19,164.79 32.1,164.88 27.62,164.88 27.52,164.79 27.52,161.03 27.18,160.69 26.62,160.69 24.49,162.82 24.49,164.3 24.59,164.4 25.55,164.4 25.76,164.6 25.76,164.91 24,166.66 24,166.79 24.1,166.89 24.23,166.89 26.42,164.69 26.55,164.69 26.65,164.79 26.65,164.92 24.45,167.11 24.45,167.24 24.55,167.34 24.68,167.34 26.87,165.15 27,165.15 27.1,165.24 27.1,165.37 24.68,167.79 24.55,167.79 23.78,167.02 23.64,167.02 23.27,167.39 23.27,170.26 24.12,171.12 24.12,173.9 24.03,173.99 23.9,173.99 23.8,173.9 23.8,172.16 23.71,172.07 23.58,172.07 23.48,172.16 23.48,174.22 23.58,174.31 24.03,174.31 24.12,174.41 24.12,183.01 25.58,184.47 v1(25.58,185.48)
MCASP1_AXR2: length 186.7
  TOP w0.178: v1(26.58,186.42) 26.08,185.92 U2.35 ; J1.11 v1(84.03,97.01)
  L08_SIG2 w0.107: v1(84.03,97.01) 84.53,97.5 84.53,99.41 75.6,108.34 75.64,108.38 75.64,117.16 75.73,117.25 75.87,117.25 75.96,117.16 75.96,108.65 76.05,108.55 76.19,108.55 76.28,108.65 76.28,117.16 76.38,117.25 76.51,117.25 76.6,117.16 76.6,108.65 76.7,108.55 76.83,108.55 76.92,108.65 76.92,117.48 76.83,117.57 75.73,117.57 75.64,117.66 75.64,118.26 76.56,119.18 76.96,119.18 77.68,119.89 77.68,122.08 75.54,124.22 75.54,128 74.75,128.79 73.2,128.79 71.62,130.37 69.65,130.37 68.59,131.43 68.59,133.21 68.07,133.73 68.07,138.54 67.4,139.21 55.44,139.21 55.34,139.3 55.34,139.44 55.44,139.53 59.75,139.53 59.84,139.62 59.84,139.76 59.75,139.85 55.12,139.85 55.02,139.76 55.02,139.3 54.93,139.21 54.4,139.21 52.53,141.08 50.8,141.08 46.39,145.49 46.39,151.38 43.11,154.66 41.98,154.66 41.36,154.04 35.55,154.04 34.7,154.9 34.09,154.9 33.99,155 33.99,156.61 33.33,157.26 33.33,163.76 32.54,164.55 32.5,164.55 32.5,164.92 32.22,165.19 27.71,165.19 26.01,166.9 26.01,170.95 25.78,171.18 25.02,171.18 24.43,171.76 24.43,173.49 25.25,174.3 25.25,183.5 26.07,184.32 26.07,185.91 v1(26.58,186.42)
MCASP1_AXR3: length 187
  TOP w0.178: J1.7 v1(84.03,96.01) ; U2.34 v1(26.58,185.48)
  L08_SIG2 w0.107: v1(26.58,185.48) 26.67,185.48 27.69,184.46 27.69,184.16 27.59,184.06 27.14,184.06 27.05,183.97 27.05,183.39 27.14,183.29 27.27,183.29 27.37,183.39 27.37,183.65 27.46,183.74 27.59,183.74 27.69,183.65 27.69,182.33 27.53,182.18 26.62,182.18 26.52,182.08 26.52,181.06 26.62,180.96 27.43,180.96 27.69,180.7 27.69,179.84 27.48,179.64 26.62,179.64 26.52,179.53 26.52,178.57 26.67,178.42 27.99,178.42 28.25,178.16 28.25,178.03 26.12,175.9 26.12,175.76 27.88,174.01 28.01,174.01 28.1,174.1 28.1,174.23 26.57,175.76 26.57,175.9 26.67,175.99 26.8,175.99 28.33,174.46 28.46,174.46 28.56,174.55 28.56,174.69 27.02,176.22 27.02,176.35 27.12,176.44 27.25,176.44 28.78,174.91 28.91,174.91 29.01,175.01 29.01,175.14 27.48,176.67 27.48,176.8 27.57,176.89 27.7,176.89 29.23,175.36 29.37,175.36 29.46,175.46 29.46,175.59 27.93,177.12 27.93,177.25 28.02,177.35 28.16,177.35 29.69,175.82 29.82,175.82 29.91,175.91 29.91,176.04 28.38,177.57 28.38,177.71 28.48,177.8 28.61,177.8 33.08,173.33 33.08,173.2 32.3,172.43 32.3,172.29 34.36,170.24 34.49,170.24 34.59,170.33 34.59,170.46 32.76,172.29 32.76,172.43 32.85,172.52 32.98,172.52 34.81,170.69 34.95,170.69 35.04,170.78 35.04,170.92 33.21,172.75 33.21,172.88 33.3,172.97 33.44,172.97 36.3,170.11 36.3,168.56 36.39,168.47 37.48,168.47 37.58,168.37 37.58,166.57 37.48,166.48 37.35,166.48 37.26,166.57 37.26,168.05 37.16,168.15 37.03,168.15 36.94,168.05 36.94,166.57 36.84,166.48 36.71,166.48 36.62,166.57 36.62,168.05 36.52,168.15 36.39,168.15 36.3,168.05 36.3,161.43 38.58,159.14 47.88,159.14 49.98,157.04 49.98,153.86 62.83,141.02 73.88,141.02 82.68,132.22 82.68,129.6 79.6,126.53 79.6,104.86 84.84,99.63 84.84,96.81 v1(84.03,96.01)
MCASP1_AXR5: length 186.3
  TOP w0.178: v1(27.58,186.42) 27.08,185.92 U2.33 ; v1(83,47.13) 83.5,46.63 J2.7
  L08_SIG2 w0.107: v1(27.58,186.42) 28.07,185.93 28.07,178.82 31.06,175.83 35.53,175.83 39.78,171.58 39.78,165.11 39.27,164.6 39.27,161.04 40.84,159.47 48.18,159.47 50.44,157.2 50.44,154.64 61.72,143.37 64.28,143.37 66.31,141.33 74.08,141.33 83.03,132.38 83.03,129.5 79.97,126.44 79.97,104.94 87.55,97.35 87.55,55.56 83.77,51.77 83.77,47.9 v1(83,47.13)
MCASP1_AXR6: length 185.6
  TOP w0.178: U2.26 v1(30.76,181.73) ; J2.9 v1(84.03,47.13)
  L08_SIG2 w0.107: v1(30.76,181.73) 29.22,181.73 28.71,181.23 28.71,179.62 30.99,177.35 34.44,177.35 40.71,171.08 40.71,162.06 42.97,159.8 48.29,159.8 66.43,141.65 79.27,141.65 83.39,137.54 83.39,129.4 80.31,126.32 80.31,105.04 81.02,104.33 84.42,104.33 89.52,99.23 89.52,95.83 89.83,95.52 89.83,56.01 87.38,53.55 87.38,48.04 86.47,47.13 v1(84.03,47.13)
MCASP1_AXR7: length 184.8
  TOP w0.178: v1(83.26,120.51) 83.27,120.51 J1.85 ; U2.25 30.08,181.23 v1(30.1,181.21)
  L08_SIG2 w0.107: v1(30.1,181.21) 30.94,181.21 31.45,181.72 33.73,181.72 34.19,182.18 34.19,182.84 33.32,183.7 31.18,183.7 30.87,184.01 30.87,186.69 30.64,186.92 30.64,188.47 30.75,188.58 30.9,188.58 30.99,188.48 30.99,187.39 31.09,187.3 34.86,187.3 34.95,187.39 34.95,187.52 34.86,187.62 31.41,187.62 31.31,187.71 31.31,187.84 31.41,187.94 34.86,187.94 34.95,188.03 34.95,188.16 34.86,188.26 31.41,188.26 31.31,188.35 31.31,188.48 31.41,188.58 35.97,188.58 36.06,188.48 36.06,186.75 36.16,186.66 37.88,186.66 37.97,186.75 37.97,186.88 37.88,186.98 36.48,186.98 36.38,187.07 36.38,187.2 36.48,187.3 37.88,187.3 37.97,187.39 37.97,187.52 37.88,187.62 36.48,187.62 36.38,187.71 36.38,187.84 36.48,187.94 37.88,187.94 37.97,188.03 37.97,188.16 37.88,188.26 36.48,188.26 36.38,188.35 36.38,188.48 36.48,188.58 39.07,188.58 39.17,188.48 39.17,186.11 39.26,186.02 40.58,186.02 40.67,186.11 40.67,186.24 40.58,186.34 39.58,186.34 39.49,186.43 39.49,186.56 39.58,186.66 40.58,186.66 40.67,186.75 40.67,186.88 40.58,186.98 39.58,186.98 39.49,187.07 39.49,187.2 39.58,187.3 40.58,187.3 40.67,187.39 40.67,187.52 40.58,187.62 39.58,187.62 39.49,187.71 39.49,187.84 39.58,187.94 40.58,187.94 40.67,188.03 40.67,188.16 40.58,188.26 39.58,188.26 39.49,188.35 39.49,188.48 39.58,188.58 41.1,188.58 41.5,188.17 41.5,185.99 44.45,183.04 44.45,182.12 44.36,182.02 43.26,182.02 43.17,181.93 43.17,180.05 43.26,179.96 43.4,179.96 43.49,180.05 43.49,181.61 43.58,181.7 43.72,181.7 43.81,181.61 43.81,180.05 43.9,179.96 44.04,179.96 44.13,180.05 44.13,181.61 44.22,181.7 44.36,181.7 44.45,181.61 44.45,179.74 43.94,179.23 41.66,179.23 41.2,178.77 41.2,177.71 43.38,175.52 43.38,172.58 45.06,170.9 45.06,168.16 44.65,167.75 43.43,167.75 41.99,166.31 41.99,162.89 43.89,160.99 48.16,160.99 65.46,143.7 80.72,143.7 84.61,139.81 84.61,120.86 84.25,120.51 v1(83.26,120.51)
MCASP1_AXR8: length 186.2
  TOP w0.178: v1(82.55,120.52) 82.55,120.19 82.73,120.01 J1.83 ; U2.23 30.13,180.23 v1(30.35,180.01)
  L08_SIG2 w0.107: v1(30.35,180.01) 33.79,180.01 34.7,180.91 34.7,184.31 34.09,184.92 32.87,184.92 32.36,185.43 32.36,186.09 32.92,186.65 34.9,186.65 35.61,185.94 38,185.94 38.51,185.43 38.51,185.07 38.41,184.97 35.4,184.97 35.31,184.88 35.31,183.08 35.4,182.99 35.53,182.99 35.63,183.08 35.63,184.56 35.72,184.65 35.85,184.65 35.95,184.56 35.95,183.08 36.04,182.99 36.17,182.99 36.27,183.08 36.27,184.56 36.36,184.65 36.49,184.65 36.59,184.56 36.59,183.08 36.68,182.99 36.81,182.99 36.91,183.08 36.91,184.56 37,184.65 37.13,184.65 37.23,184.56 37.23,183.08 37.32,182.99 37.45,182.99 37.55,183.08 37.55,184.56 37.64,184.65 37.77,184.65 37.87,184.56 37.87,183.08 37.96,182.99 38.09,182.99 38.19,183.08 38.19,184.56 38.28,184.65 38.41,184.65 38.51,184.56 38.51,181.87 38.76,181.62 38.98,181.62 39.08,181.52 39.08,180.43 39.17,180.34 42.05,180.34 42.15,180.43 42.15,180.56 42.05,180.66 39.49,180.66 39.4,180.75 39.4,180.88 39.49,180.98 42.05,180.98 42.15,181.07 42.15,181.2 42.05,181.3 39.49,181.3 39.4,181.39 39.4,181.52 39.49,181.62 42.37,181.62 42.62,181.36 42.62,180.15 42.32,179.84 40.59,179.84 40.39,179.64 40.39,179.28 40.12,179.02 37.92,179.02 37.83,178.92 37.83,175.89 37.92,175.79 38.05,175.79 38.15,175.89 38.15,178.6 38.24,178.7 38.37,178.7 38.47,178.6 38.47,175.89 38.56,175.79 38.69,175.79 38.79,175.89 38.79,178.6 38.88,178.7 39.01,178.7 39.11,178.6 39.11,175.89 39.2,175.79 39.33,175.79 39.43,175.89 39.43,178.6 39.52,178.7 39.65,178.7 39.75,178.6 39.75,175.89 39.84,175.79 39.97,175.79 40.07,175.89 40.07,178.6 40.16,178.7 40.29,178.7 40.39,178.6 40.39,175.57 41.68,174.28 41.68,171.56 42.27,170.98 42.27,167.12 41.68,166.54 41.68,161.53 43.03,160.18 48.39,160.18 66.6,141.97 79.46,141.97 83.72,137.71 83.72,129.24 81.79,127.31 81.79,120.91 82.18,120.52 v1(82.55,120.52)
MCASP2_AXR0: length 10.7
  TOP w0.178: R119.1 v1(76.11,124.87) ; v1(83.31,123.02) 83.82,122.51 J1.93
  BOTTOM w0.178: v1(83.31,123.02) 77.96,123.02 v1(76.11,124.87)
MCASP6_ACLKR: length 46.2
  TOP w0.178: R124.1 v1(52.5,123.95) ; J1.92 92.66,122.01 v1(93.5,122.84)
  BOTTOM w0.178: v1(93.5,122.84) 92.99,123.35 87.07,123.35 85.8,122.08 77.47,122.08 74.98,124.57 53.12,124.57 v1(52.5,123.95)
MCASP6_ACLKX: length 19.1
  TOP w0.178: R123.1 51.26,123.6 52.5,122.36 57.99,122.36 58.36,122.73 67.18,122.73 67.46,122.45 U17.5
MCASP6_AFSR: length 38.7
  TOP w0.178: R126.1 v1(54.99,123.95)
  BOTTOM w0.178: R536.2 87.34,117.94 86.53,118.75 70.79,118.75 70.35,119.2 70.35,122.91 69.06,124.19 55.23,124.19 v1(54.99,123.95)
MCASP6_AFSX: length 20.8
  TOP w0.178: R125.1 53.75,123.72 54.6,122.87 v1(57.33,122.87) ; U17.11 v1(66.81,117.22)
  BOTTOM w0.178: v1(66.81,117.22) 66.29,117.74 66.29,122.36 65.79,122.87 v1(57.33,122.87)
MCASP6_AXR0: length 23.6
  TOP w0.178: R121.1 v1(48.77,123.57) ; U17.2 v1(69.41,122.49)
  BOTTOM w0.178: v1(69.41,122.49) 68.5,123.4 56.21,123.4 55.78,122.97 49.37,122.97 v1(48.77,123.57)
MCASP6_AXR1: length 1.9
  TOP w0.178: U17.14 v1(68.76,113.83)
MCASP6_MUX_SEL: length 18.6
  TOP w0.178: U15.17 60.78,123.8 61.33,123.25 70.61,123.25 71.34,122.53 v1(71.34,122.45) R130.2 U17.1
MCASP10_ACLKX/EHRPWM0_SYNCI: length 10.4
  TOP w0.178: J2.41 v1(83.64,55.13)
  L03_SIG1 w0.107: J10.2 78.33,58.17 78.61,57.89 78.61,56.31 79.63,55.29 80.58,55.29 81.26,54.62 83.12,54.62 v1(83.64,55.13)
MCASP10_AFSX/EHRPWM0_SYNCO: length 12.5
  TOP w0.178: v1(82.6,55.13) 83.1,55.63 J2.43
  L03_SIG1 w0.107: J10.3 78.59,60.71 78.93,60.37 78.93,56.62 79.88,55.67 81.79,55.67 82.33,55.13 v1(82.6,55.13)
MCASP10_AXR0/EHRPWM_TZN_IN0: length 14.6
  TOP w0.178: J2.45 v1(83.64,56.13)
  L03_SIG1 w0.107: J10.4 78.84,63.25 79.31,62.78 79.31,56.88 80.2,55.99 81.97,55.99 82.33,55.63 83.14,55.63 v1(83.64,56.13)
MCASP10_AXR1/EHRPWM0_A: length 16.6
  TOP w0.178: v1(82.6,56.13) 82.87,56.13 83.37,56.63 J2.47
  L03_SIG1 w0.107: v1(82.6,56.13) 82.42,56.31 80.45,56.31 79.69,57.07 79.69,65.07 78.97,65.79 J10.5
MCASP10_AXR2/EHRPWM1_B: length 19.1
  TOP w0.178: J2.51 v1(83.52,57.63)
  L03_SIG1 w0.107: v1(83.52,57.63) 82.52,56.62 80.71,56.62 80.14,57.2 80.14,67.67 79.48,68.33 J10.6
MCASP10_AXR3/EHRPWM_TZN_IN1: length 11.3
  TOP w0.178: J10.1 79.53,55.63 79.95,56.05 79.95,59.23 80.35,59.63 J2.59
MCASP11_ACLKX: length 28.5
  TOP w0.178: J2.49 v1(81.03,57.13)
  L03_SIG1 w0.107: v1(81.03,57.13) 82.06,57.13 83.06,58.12 83.97,58.12 84.58,57.51 94.1,57.51 97.23,60.64 97.23,61.78 97.49,62.04 v1(97.49,64.32)
  BOTTOM w0.178: v1(97.49,64.32) 97.49,65.2 R235.2
MCASP11_AFSX: length 29.9
  TOP w0.178: J2.53 v1(81.03,58.13)
  L03_SIG1 w0.107: v1(81.03,58.13) 81.03,58.94 81.23,59.14 81.84,59.14 82.09,58.89 82.09,58.68 82.3,58.48 84.12,58.48 84.73,57.87 86.77,57.87 87.68,58.78 88.49,58.78 89.41,57.87 93.98,57.87 96.88,60.77 96.88,61.93 97.13,62.19 97.13,63.66 v1(96.47,64.32)
  BOTTOM w0.178: R233.2 95.21,65.57 95.39,65.39 95.4,65.39 v1(96.47,64.32)
MCASP11_AXR0: length 33.8
  TOP w0.178: J2.55 83.5,58.63 v1(83,59.13)
  L03_SIG1 w0.107: v1(83,59.13) 83.5,59.63 84,59.63 84.62,60.25 84.62,60.7 84.71,60.8 90.58,60.8 90.68,60.7 90.68,60.57 90.58,60.48 85.03,60.48 84.94,60.38 84.94,60.25 85.03,60.16 91.08,60.16 92.15,61.22 92.15,64.08 92.06,64.17 91.92,64.17 91.83,64.08 91.83,63.8 91.73,63.71 91.5,63.71 91.39,63.82 91.39,64.39 93.17,66.17 v1(93.5,66.17)
  BOTTOM w0.178: J17.37 v1(93.5,66.17)
MCASP11_AXR1: length 33.8
  TOP w0.178: J2.61 83.5,65.13 v1(83,65.63)
  L03_SIG1 w0.107: v1(83,65.63) 83.52,66.15 85.14,66.15 85.65,65.64 85.65,62.54 85.8,62.39 86.41,62.39 86.52,62.5 86.52,63.58 86.62,63.67 89.26,63.67 89.36,63.58 89.36,63.44 89.26,63.35 86.94,63.35 86.84,63.26 86.84,63.12 86.94,63.03 89.26,63.03 89.36,62.94 89.36,62.8 89.26,62.71 86.94,62.71 86.84,62.62 86.84,62.48 86.94,62.39 90.07,62.39 90.22,62.54 90.22,64.81 91.95,66.54 91.95,66.91 92.68,67.64 v1(93.5,67.64)
  BOTTOM w0.178: v1(93.5,67.64) 93.38,67.77 J17.33
MCASP11_AXR2: length 33.4
  TOP w0.178: J2.57 v1(84.03,59.13)
  L03_SIG1 w0.107: v1(94.39,66.17) 93.31,65.09 93.31,59.3 93.22,59.21 93.09,59.21 92.99,59.3 92.99,63.57 92.9,63.66 92.77,63.66 92.67,63.57 92.67,58.98 92.77,58.89 93.22,58.89 93.31,58.8 93.31,58.58 92.96,58.23 90.02,58.23 89.87,58.38 89.87,59.54 89.76,59.65 88.11,59.65 86.64,58.18 84.98,58.18 v1(84.03,59.13)
  BOTTOM w0.178: v1(94.39,66.17) 93.59,65.37 J17.39
MCASP11_AXR3: length 33.3
  TOP w0.178: J2.63 v1(84.03,65.63)
  L03_SIG1 w0.107: v1(94.39,67.65) 93.9,67.17 93.01,67.17 90.68,64.83 90.68,61.83 90.07,61.22 86,61.22 85.91,61.32 85.91,61.45 86,61.54 89.37,61.54 89.46,61.64 89.46,61.77 89.37,61.86 85.68,61.86 85.59,61.77 85.59,61.32 85.5,61.22 82.91,61.22 82.09,62.04 82.09,63.69 v1(84.03,65.63)
  BOTTOM w0.178: J17.35 93.71,66.97 v1(94.39,67.65)
MCASP11_AXR4: length 33.3
  TOP w0.178: J2.52 93.05,57.63 93.92,58.5 v1(93.92,61.72)
  L03_SIG1 w0.107: v1(94.52,72.57) 94.05,72.09 93.73,72.09 91.19,74.63 89.56,74.63 89.26,74.33 89.26,73.62 89.53,73.34 91.35,73.34 94.51,70.18 94.52,70.18 95.86,68.84 95.86,63.05 94.53,61.72 v1(93.92,61.72)
  BOTTOM w0.178: v1(94.52,72.57) 93.72,71.77 J17.23
MCASP11_AXR5: length 33.8
  TOP w0.178: J2.42 93.17,55.13 95.5,57.46 95.5,63.76 v1(94.49,64.78)
  L03_SIG1 w0.107: v1(94.49,64.78) 95.2,65.49 95.2,68.61 92.04,71.77 v1(83,71.77)
  BOTTOM w0.178: J17.24 v1(83,71.77)
MCASP11_AXR6: length 32.6
  TOP w0.178: J2.48 92.94,56.63 94.46,58.15 v1(94.46,62.75)
  L03_SIG1 w0.107: v1(94.46,62.75) 95.53,63.81 95.53,68.73 91.22,73.03 v1(83,73.03)
  BOTTOM w0.178: v1(83,73.03) 83.46,72.57 J17.22
MCASP11_AXR7: length 31.9
  TOP w0.178: J2.44 92.81,55.63 94.98,57.81 94.98,63.27 94.5,63.75 v1(93.92,63.75)
  L03_SIG1 w0.107: v1(93.92,63.75) 93.92,64.87 94.87,65.82 94.87,67.95 94.66,68.16 84.52,68.16 v1(83,66.63)
  BOTTOM w0.178: v1(83,66.63) 83.46,66.17 J17.38
MCASP_ACLKR_BUF: length 2.7
  TOP w0.178: U14.7 52.06,126.86 52.5,126.42 R124.2
MCASP_ACLKX_BUF: length 2.6
  TOP w0.178: R123.2 51.26,126.68 51.41,126.84 U14.6
MCASP_AFSR_BUF: length 2.9
  TOP w0.178: U14.10 54.01,126.84 54.99,125.87 R126.2
MCASP_AFSX_BUF: length 2.7
  TOP w0.178: U14.9 53.36,126.68 53.75,126.3 R125.2
MCASP_AXR0_BUF: length 2.8
  TOP w0.178: R121.2 48.77,126.07 49.46,126.77 U14.3
MIC1AL_A: length 2.7
  TOP w0.381: U27.7 33.58,65.81 33.45,65.94 C143.2 33.45,67.49 R219.1
MIC1AL_AC: length 1.2
  TOP w0.381: C147.1 R228.1
MIC1AL_B: length 7.8
  TOP w0.381: R220.1 34.38,66.43 C143.1 34.37,65.92 34.23,65.78 U27.6 34.23,62.95 33.53,62.24 R228.2
MIC1AL_BIAS: length 2.5
  TOP w0.381: C151.2 R230.2 R232.2
MIC1AL_BIAS_AC: length 6.4
  TOP w0.381: C148.1 22.62,62.09 R229.1 22.46,60.89 U28.6 22.46,58.82 22.08,58.44 C151.1
MIC1AL_C: length 8.3
  TOP w0.381: R224.1 37.65,59.76 36.9,59.01 R231.1 34.95,59.09 C150.1 33.72,59.56 33.58,59.69 U27.2
MIC1AL_D: length 2.7
  TOP w0.381: U27.1 32.93,59.7 32.8,59.56 C150.2 32.8,57.99 R234.1
MIC1AL_PRE: length 3.7
  TOP w0.381: U28.7 21.81,60.89 R229.2 21.64,62.09 C148.2 21.64,62.15 R223.1
MIC1AR_A: length 2.5
  TOP w0.381: U29.7 33.58,55.22 33.45,55.36 C154.2 33.45,56.73 R236.1
MIC1AR_AC: length 1.2
  TOP w0.381: C158.1 R241.1
MIC1AR_B: length 7.1
  TOP w0.381: R241.2 33.77,52.39 34.23,52.86 U29.6 34.23,55.16 34.37,55.3 C154.1 35.58,55.75 R238.1
MIC1AR_BIAS: length 2.5
  TOP w0.381: C153.2 R239.2 R237.2
MIC1AR_BIAS_AC: length 6
  TOP w0.381: R240.1 21.97,53.67 C156.1 21.81,53.83 U28.2 21.81,56.08 21.43,56.46 C153.1
MIC1AR_C: length 8.3
  TOP w0.381: R242.1 37.65,49.06 37,48.41 R256.1 33.77,48.41 C163.1 33.58,48.59 U29.2
MIC1AR_D: length 2.7
  TOP w0.381: R257.1 32.8,47.36 C163.2 32.93,48.59 U29.1
MIC1AR_PRE: length 3.9
  TOP w0.381: U28.1 21.16,53.83 C156.2 20.99,53.67 R240.2 R247.1
MIC1BL_A: length 2.7
  TOP w0.381: U20.7 33.58,98.74 33.45,98.88 C98.2 33.45,100.47 R172.1
MIC1BL_AC: length 1.3
  TOP w0.381: R180.1 C105.1
MIC1BL_B: length 7.1
  TOP w0.381: R180.2 33.09,95.43 34.23,96.57 U20.6 34.23,98.72 34.37,98.85 C98.1 35.43,99.36 R173.1
MIC1BL_BIAS: length 2.5
  TOP w0.381: C111.2 R182.2 R185.2
MIC1BL_BIAS_AC: length 6.6
  TOP w0.381: C106.1 22.62,95.23 R181.1 22.62,93.6 22.46,93.44 U22.6 22.46,91.74 22.08,91.36 C111.1
MIC1BL_C: length 8.3
  TOP w0.381: U20.2 33.58,92.58 33.72,92.45 C108.1 33.72,91.97 R184.1 37,91.97 37.65,92.62 R179.1
MIC1BL_D: length 2.7
  TOP w0.381: U20.1 32.93,92.61 32.8,92.48 C108.2 32.8,90.92 R186.1
MIC1BL_PRE: length 3.9
  TOP w0.381: U22.7 21.81,93.45 21.64,93.62 R181.2 21.64,95.23 C106.2 21.64,95.29 R175.1
MIC1BR_A: length 2.7
  TOP w0.381: U23.7 33.58,88.15 33.45,88.28 C115.2 33.45,89.83 R189.1
MIC1BR_AC: length 1.3
  TOP w0.381: C118.1 R194.1
MIC1BR_B: length 7
  TOP w0.381: R191.1 34.45,88.81 C115.1 34.37,88.26 34.23,88.12 U23.6 34.23,85.96 33.85,85.58 R194.2
MIC1BR_BIAS: length 2.5
  TOP w0.381: C114.2 R192.2 R190.2
MIC1BR_BIAS_AC: length 5.8
  TOP w0.381: C114.1 21.43,89.38 21.81,89 U22.2 21.81,87.34 21.94,87.21 C117.1 21.94,85.68 R193.1
MIC1BR_C: length 8.3
  TOP w0.381: U23.2 33.58,82.02 33.72,81.89 C121.1 33.77,81.32 R203.1 36.78,81.32 37.65,82.18 R198.1
MIC1BR_D: length 2.7
  TOP w0.381: R204.1 32.8,80.26 C121.2 32.8,81.86 32.93,82 U23.1
MIC1BR_PRE: length 3.6
  TOP w0.381: R199.1 R193.2 21.02,85.68 C117.2 21.02,87.22 21.16,87.35 U22.1
MIC2AL_A: length 2.5
  BOTTOM w0.381: R469.1 32.8,56.78 C351.2 32.8,55.32 32.93,55.19 U55.1
MIC2AL_AC: length 1.2
  BOTTOM w0.381: R476.1 C354.1
MIC2AL_B: length 6.5
  BOTTOM w0.381: R471.1 34.88,55.8 C351.1 33.72,55.32 33.58,55.19 U55.2 33.58,52.81 33.16,52.39 R476.2
MIC2AL_BIAS: length 2.5
  BOTTOM w0.381: R470.2 R472.2 C350.2
MIC2AL_BIAS_AC: length 6.7
  BOTTOM w0.381: C350.1 22.14,56.46 22.46,56.14 U54.6 22.46,53.86 R474.1 22.62,52.59 C353.1
MIC2AL_C: length 7.7
  BOTTOM w0.381: U55.6 34.23,48.59 C358.1 35.63,48.46 R489.1 37,48.41 37.65,49.06 R477.1
MIC2AL_D: length 2.7
  BOTTOM w0.381: U55.7 33.58,48.59 C358.2 33.45,47.36 R490.1
MIC2AL_PRE: length 3.9
  BOTTOM w0.381: R481.1 21.64,52.53 C353.2 21.64,52.59 R474.2 21.81,53.86 U54.7
MIC2AR_A: length 2.6
  BOTTOM w0.381: R453.1 32.8,67.49 C339.2 32.8,65.99 32.93,65.85 U53.1
MIC2AR_AC: length 1.2
  BOTTOM w0.381: C342.1 R463.1
MIC2AR_B: length 7.2
  BOTTOM w0.381: R454.1 33.73,66.43 C339.1 33.72,65.97 33.58,65.83 U53.2 33.58,62.76 33.06,62.24 R463.2
MIC2AR_BIAS: length 2.5
  BOTTOM w0.381: R467.2 R465.2 C347.2
MIC2AR_BIAS_AC: length 5.8
  BOTTOM w0.381: R464.1 21.97,61.11 C343.1 21.94,60.64 21.81,60.51 U54.2 21.81,58.71 21.54,58.44 C347.1
MIC2AR_C: length 7.7
  BOTTOM w0.381: R459.1 37.65,59.73 36.93,59.01 R466.1 35.6,59.09 C345.1 34.37,59.57 34.23,59.71 U53.6
MIC2AR_D: length 2.7
  BOTTOM w0.381: U53.7 33.58,59.71 33.45,59.58 C345.2 33.45,57.99 R468.1
MIC2AR_PRE: length 3.6
  BOTTOM w0.381: U54.1 21.16,60.47 21.02,60.61 C343.2 20.99,61.11 R464.2 R458.1
MIC2BL_A: length 2.8
  BOTTOM w0.381: R429.1 32.8,89.92 C319.2 32.8,88.28 32.93,88.15 U50.1
MIC2BL_AC: length 1.3
  BOTTOM w0.381: R435.1 C322.1
MIC2BL_B: length 6.4
  BOTTOM w0.381: R431.1 33.82,88.91 C319.1 33.72,88.31 33.58,88.17 U50.2 33.58,86.02 33.15,85.58 R435.2
MIC2BL_BIAS: length 2.5
  BOTTOM w0.381: C318.2 R432.2 R430.2
MIC2BL_BIAS_AC: length 6.4
  BOTTOM w0.381: C318.1 22.14,89.38 22.46,89.06 U49.6 22.46,87.31 22.62,87.14 R433.1 22.62,85.73 C321.1
MIC2BL_C: length 7.6
  BOTTOM w0.381: R439.1 37.65,82.19 36.78,81.32 R443.1 34.42,81.32 C326.1 34.37,81.86 34.23,81.99 U50.6
MIC2BL_D: length 2.7
  BOTTOM w0.381: R444.1 33.45,80.26 C326.2 33.45,81.89 33.58,82.02 U50.7
MIC2BL_PRE: length 3.7
  BOTTOM w0.381: U49.7 21.81,87.33 21.64,87.17 R433.2 21.64,85.73 C321.2 21.67,84.63 R440.1
MIC2BR_A: length 2.8
  BOTTOM w0.381: U48.1 32.93,98.76 32.8,98.9 C307.2 32.84,99.43 R416.1
MIC2BR_AC: length 1.3
  BOTTOM w0.381: C310.1 R423.1
MIC2BR_B: length 7
  BOTTOM w0.381: R417.1 33.79,99.46 C307.1 33.72,98.91 33.58,98.78 U48.2 33.58,95.92 33.09,95.43 R423.2
MIC2BR_BIAS: length 2.5
  BOTTOM w0.381: C316.2 R425.2 R427.2
MIC2BR_BIAS_AC: length 6
  BOTTOM w0.381: R424.1 21.97,94.15 C313.1 21.94,93.56 21.81,93.43 U49.2 21.81,91.63 21.54,91.36 C316.1
MIC2BR_C: length 7.6
  BOTTOM w0.381: R422.1 37.65,92.62 37.05,92.02 R426.1 35.68,92.03 C315.1 34.37,92.49 34.23,92.62 U48.6
MIC2BR_D: length 2.6
  BOTTOM w0.381: U48.7 33.58,92.64 33.45,92.5 C315.2 33.45,90.97 R428.1
MIC2BR_PRE: length 3.9
  BOTTOM w0.381: U49.1 21.16,93.44 21.02,93.57 C313.2 20.99,94.15 R424.2 R418.1
MODE_SEL: length 4.1
  TOP w0.178: R17.2 30.76,175.5 R16.1 30.01,175.43 29.56,175.88 U2.15
MUX_MCASP6_ACLKX: length 33.5
  TOP w0.178: v1(93.44,120.51) 92.94,120.01 J1.84 ; U17.7 66.16,119.09 66.37,118.88 71.88,118.88 v1(72.8,119.79)
  BOTTOM w0.178: v1(72.8,119.79) 73.36,119.24 88.36,119.24 90.14,121.01 92.94,121.01 v1(93.44,120.51)
MUX_MCASP6_AFSX: length 34.9
  TOP w0.178: v1(74.52,120.51) 74.3,120.51 72.06,118.27 65.69,118.27 65.51,118.09 U17.9 ; v1(93.44,121.51) 92.94,121.01 J1.88
  BOTTOM w0.178: v1(93.44,121.51) 92.92,122.03 89.63,122.03 87.6,120 75.36,120 74.85,120.51 v1(74.52,120.51)
MUX_MCASP6_AXR0: length 28.6
  TOP w0.178: v1(92.46,122.56) 92.4,122.51 J1.94 ; v1(72.8,120.53) 71.56,119.3 68.57,119.3 68.11,119.76 U17.4
  BOTTOM w0.178: v1(72.8,120.53) 73.28,121.01 87.96,121.01 89.51,122.56 v1(92.46,122.56)
MUX_MCASP6_AXR1: length 29.5
  TOP w0.178: J1.90 v1(92.41,121.51) ; U17.12 67.46,117.3 67.89,117.74 72.26,117.74 v1(74.32,119.79)
  BOTTOM w0.178: v1(92.41,121.51) 89.9,121.51 88.01,119.62 74.5,119.62 v1(74.32,119.79)
OEN: length 2.4
  TOP w0.178: U2.31 28.39,184.58 28.64,184.83 28.97,184.83 29.27,184.53 30.17,184.53 R8.1
OSS_SEL: length 2.9
  TOP w0.178: R6.1 19.72,184.45 20.23,183.94 U2.46
OV_CAM_PWDN: length 12.2
  TOP w0.178: v1(40.83,184.39) 40.26,183.82 40.26,176.82 38.49,175.05 U3.6
  BOTTOM w0.178: R318.2 40.84,184.39 v1(40.83,184.39)
OV_VIN_DATA0: length 66.5
  TOP w0.203: v1(57.54,176.22) 56.94,175.62 U6.36
  L03_SIG1 w0.107: J3.26 13.7,187.71 32.42,187.71 34.72,185.42 34.72,182.28 34.63,182.19 34.03,182.19 33.93,182.1 33.93,181.96 34.03,181.87 34.63,181.87 34.72,181.78 34.72,181.64 34.63,181.55 34.03,181.55 33.93,181.46 33.93,181.32 34.03,181.23 34.63,181.23 34.72,181.14 34.72,181 34.63,180.91 34.03,180.91 33.93,180.82 33.93,180.68 34.03,180.59 34.63,180.59 34.72,180.5 34.72,180.36 34.63,180.27 34.03,180.27 33.93,180.18 33.93,180.04 34.03,179.95 34.63,179.95 34.72,179.86 34.72,176.64 35.14,176.22 v1(57.54,176.22)
